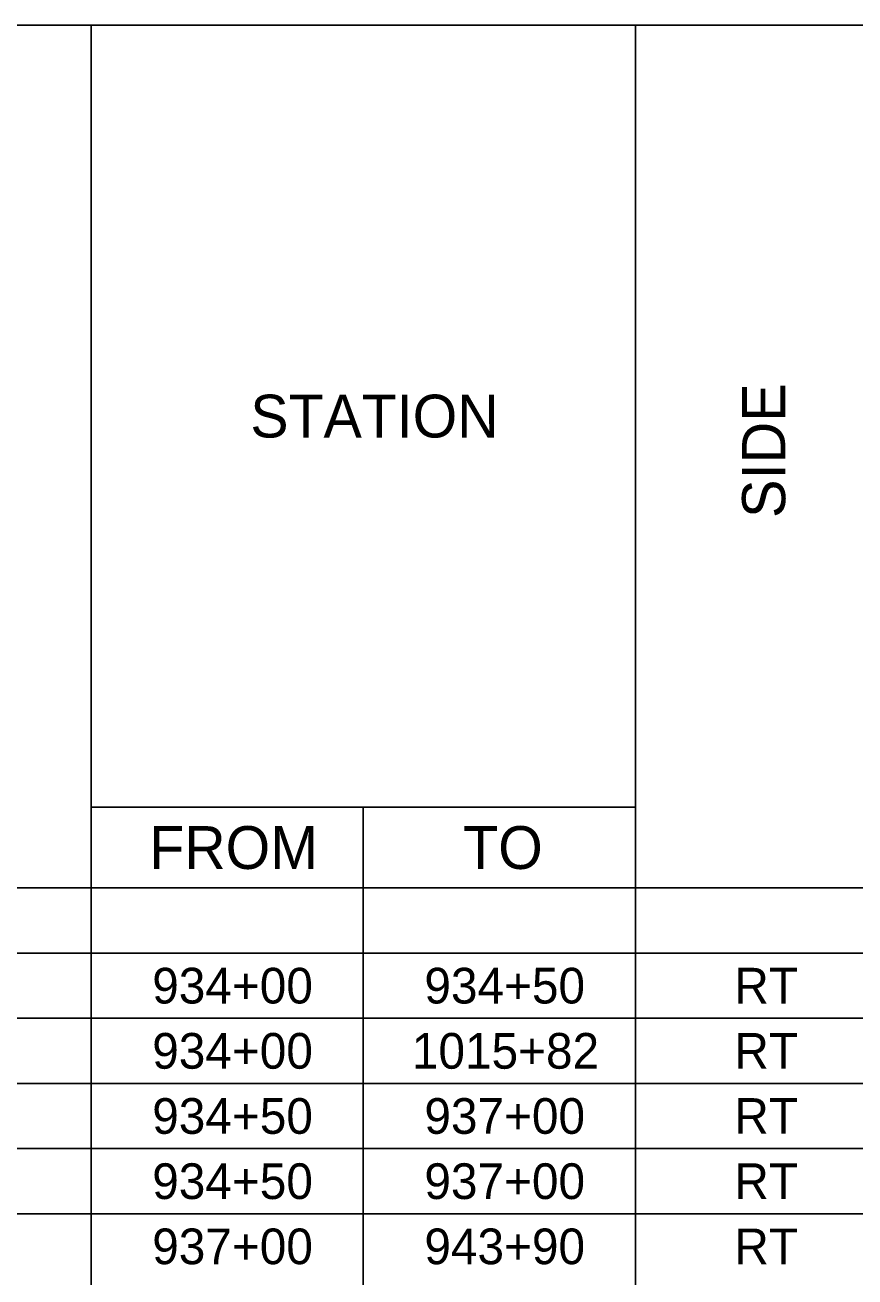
# Model space of a CAD drawing. Extents: x 91011267 to 91022583, y 37007614 to 37014266.
# Drawn here: x 91011467.7 to 91011642.6, y 37008399.9 to 37008663.8 of the extents above; entities that cross this region are included whole.
import ezdxf

# ---------------------------------------------------------------- set-up
doc = ezdxf.new("R2010")
doc.units = 0
doc.layers.add('SC_Scratch2', color=7, linetype='Continuous')
doc.layers.add('SH_Data', color=7, linetype='Continuous')

msp = doc.modelspace()

# ---------------------------------------------------------------- linework, layer by layer
at = {"layer": 'SC_Scratch2'}
msp.add_lwpolyline([(91011277.35, 37008663.81), (91012802.35, 37008663.81), (91012802.35, 37007613.81), (91011277.35, 37007613.81)], close=True, dxfattribs=at)
at = {"layer": 'SH_Data'}
for p, q in [((91011277.35, 37008663.81), (91011596.32, 37008663.81)), ((91011481.65, 37008663.81), (91011481.65, 37008572.88)), ((91011596.32, 37008663.81), (91011650.36, 37008663.81)), ((91011596.32, 37008663.81), (91011596.32, 37008572.88)), ((91011481.65, 37008572.88), (91011481.65, 37008498.95)), ((91011596.32, 37008572.88), (91011596.32, 37008498.95)), ((91011481.65, 37008498.95), (91011596.32, 37008498.95)), ((91011481.65, 37008498.95), (91011481.65, 37008481.94)), ((91011538.99, 37008498.95), (91011538.99, 37008481.94)), ((91011596.32, 37008498.95), (91011596.32, 37008481.94)), ((91011277.35, 37008481.94), (91011596.32, 37008481.94)), ((91011481.65, 37008481.94), (91011481.65, 37008372.04)), ((91011538.99, 37008481.94), (91011538.99, 37008372.04)), ((91011596.32, 37008481.94), (91011650.36, 37008481.94)), ((91011596.32, 37008481.94), (91011596.32, 37008372.04)), ((91011277.35, 37008468.2), (91011596.32, 37008468.2)), ((91011596.32, 37008468.2), (91011650.36, 37008468.2)), ((91011277.35, 37008454.47), (91011596.32, 37008454.47)), ((91011596.32, 37008454.47), (91011650.36, 37008454.47)), ((91011277.35, 37008440.73), (91011596.32, 37008440.73)), ((91011596.32, 37008440.73), (91011650.36, 37008440.73)), ((91011277.35, 37008426.99), (91011596.32, 37008426.99)), ((91011596.32, 37008426.99), (91011650.36, 37008426.99)), ((91011277.35, 37008413.25), (91011596.32, 37008413.25)), ((91011596.32, 37008413.25), (91011650.36, 37008413.25))]:
    msp.add_line(p, q, dxfattribs=at)

# ---------------------------------------------------------------- texts
for s, height, p in [('STATION', 9.028, (91011515.19, 37008576.87)), ('FROM', 9.028, (91011493.89, 37008485.93)), ('TO', 9.028, (91011560.04, 37008485.93)), ('934+00', 7.523, (91011494.52, 37008457.57)), ('934+50', 7.523, (91011551.86, 37008457.57)), ('RT', 7.523, (91011617.17, 37008457.57)), ('934+00', 7.523, (91011494.52, 37008443.83)), ('1015+82', 7.523, (91011549.23, 37008443.83)), ('RT', 7.523, (91011617.17, 37008443.83)), ('934+50', 7.523, (91011494.52, 37008430.1)), ('937+00', 7.523, (91011551.86, 37008430.1)), ('RT', 7.523, (91011617.17, 37008430.1)), ('934+50', 7.523, (91011494.52, 37008416.36)), ('937+00', 7.523, (91011551.86, 37008416.36)), ('RT', 7.523, (91011617.17, 37008416.36)), ('937+00', 7.523, (91011494.52, 37008402.62)), ('943+90', 7.523, (91011551.86, 37008402.62)), ('RT', 7.523, (91011617.17, 37008402.62))]:
    msp.add_text(s, height=height, dxfattribs=at).set_placement(p)
msp.add_text('SIDE', height=9.095, rotation=90, dxfattribs=at).set_placement((91011627.89, 37008559.91))

doc.saveas('drawing.dxf')
